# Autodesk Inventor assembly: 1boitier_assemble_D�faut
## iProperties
Created: 2011-01
Part Number: 1boitier_assemble_D�faut
Document SubType Name: Assembly
Designer: eric
Mass: 73.238 g
Surface Area: 581.356 cm^2
Volume: 73.238 cm^3
Density: 1 g/cm^3
Author: eric
